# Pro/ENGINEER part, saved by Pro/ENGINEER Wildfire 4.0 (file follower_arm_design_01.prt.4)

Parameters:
  METRIC = "NO"

Other parameters: PITCH, DRILL_DIAMETER, THREAD_DIAMETER, THREADS_PER_INCH, THREAD_DEPTH, THREAD_LENGTH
